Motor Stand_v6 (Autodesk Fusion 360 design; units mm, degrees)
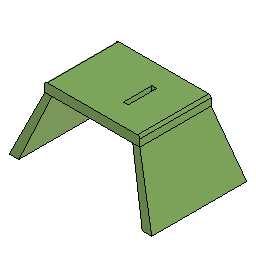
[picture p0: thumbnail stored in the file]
sketch "Sketch1" plane through (0, 0, 0) normal (0, 0, 1) x axis (1, 0, 0)
  line L1 (-20, -15) -> (20, -15)
  line L2 (-20, 15) -> (-20, -15)
  line L3 (20, 15) -> (-20, 15)
  line L4 (20, -15) -> (20, 15)
  line L5 (-20, 15) -> (20, -15)
  line L6 (20, 15) -> (-20, -15)
  line L7 (-17, -15) -> (17, -15)
  line L8 (-17, 15) -> (-17, -15)
  line L9 (17, 15) -> (-17, 15)
  line L10 (17, -15) -> (17, 15)
  line L11 (-17, 15) -> (17, -15)
  line L12 (17, 15) -> (-17, -15)
  point P6 (0, 0)
  point P1 (0, 0)
  point P11 (0, 0)
  point P4 (-20, 15)
  point P5 (20, 15)
  point P3 (-20, -15)
  point P9 (-17, 15)
  point P10 (17, 15)
  point P8 (-17, -15)
  horizontal L1
  perpendicular L1 L2
  parallel L1 L3
  parallel L2 L4
  coincident L5 P6
  coincident L6 P6
  coincident P1 P6
  horizontal L7
  perpendicular L7 L8
  parallel L7 L9
  parallel L8 L10
  coincident L11 P11
  coincident L12 P11
  coincident P1 P11
  dimension "d1" distance P4 P5 = 40
  dimension "d2" distance P3 P4 = 30
  dimension "d9" distance P9 P10 = 34 (= "d1 - 6 mm")
  dimension "d10" distance P8 P9 = 30 (= "d2")
work_plane "WorkPlane1" AlongDistance -25 ExtraOffset 0
sketch "Sketch2" plane through (0, 0, -25) normal (0, 0, 1) x axis (1, 0, 0)
  line L1 (-30, 20) -> (-30, -20)
  line L2 (30, -20) -> (30, 20)
  line L3 (-30, 20) -> (30, -20)
  line L4 (30, 20) -> (-30, -20)
  line L5 (-26, -20) -> (-26, 20)
  line L6 (26, 20) -> (26, -20)
  line L7 (-26, -20) -> (26, 20)
  line L8 (26, -20) -> (-26, 20)
  line L9 (26, -20) -> (30, -20)
  line L10 (-30, -20) -> (-26, -20)
  line L11 (-26, 20) -> (-30, 20)
  line L12 (30, 20) -> (26, 20)
  point P6 (0, 0)
  point P1 (0, 0)
  point P11 (0, 0)
  point P4 (-30, 20)
  point P5 (30, 20)
  point P3 (-30, -20)
  point P9 (-26, -20)
  point P10 (26, -20)
  point P8 (-26, 20)
  horizontal L9
  perpendicular L1 L10
  parallel L9 L12
  parallel L1 L2
  coincident L3 P6
  coincident L4 P6
  coincident P1 P6
  parallel L5 L6
  coincident L7 P11
  coincident L8 P11
  coincident P6 P11
  collinear L9 L10
  collinear L11 L12
  dimension "d5" distance P4 P5 = 60
  dimension "d6" distance P3 P4 = 40
  dimension "d7" distance P9 P10 = 52 (= "d5 - 8 mm")
  dimension "d8" distance P8 P9 = 40 (= "d6")
loft "Loft1" sketch "Sketch2" + "Sketch1"
loft "Loft2" sketch "Sketch1" + "Sketch2"
extrude "Extrude1" add sketch "Sketch1" profile of L1 L2 L3 L4 L7 L8 L9 L10 along normal blind 4
sketch "Sketch3" plane through (0, 0, 4) normal (0, 0, 1) x axis (-1, 0, 0)
  line L1 (20, -15) -> (-20, -15)
  line L2 (20, 15) -> (20, -15)
  line L3 (-20, 15) -> (20, 15)
  line L4 (-20, -15) -> (-20, 15)
  line L5 (-5.1, 15) -> (-5.1, -15)
  line L6 (-4.1, 6) -> (-6.1, 6)
  line L7 (-4.1, -6) -> (-4.1, 6)
  line L8 (-6.1, -6) -> (-4.1, -6)
  line L9 (-6.1, 6) -> (-6.1, -6)
  line L10 (-4.1, -6) -> (-6.1, 6)
  line L11 (-6.1, -6) -> (-4.1, 6)
  point P6 (-5.1, -15)
  point P12 (-5.1, 0)
  point P7 (-5.1, 15)
  point P10 (-4.1, -6)
  point P11 (-6.1, -6)
  point P9 (-4.1, 6)
  vertical L5
  coincident L1 P6
  horizontal L6
  perpendicular L6 L7
  parallel L6 L8
  parallel L7 L9
  coincident L10 P12
  coincident L11 P12
  midpoint L5 P12
  dimension "d13" distance P6 P7 = 30
  dimension "d14" distance L4 L5 = 14.9 (= "14.3 mm + ( 1.2 / 2 ) * 1 mm")
  dimension "d15" distance P10 P11 = 2
  dimension "d16" distance P9 P10 = 12
extrude "Extrude2" cut sketch "Sketch3" profile of L6 L7 L8 L9 against normal blind 4
fillet "Fillet1" radius 1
